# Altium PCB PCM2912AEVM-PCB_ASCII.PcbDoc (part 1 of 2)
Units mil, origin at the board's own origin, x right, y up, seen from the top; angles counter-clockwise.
Board outline 2362.2 x 944.88 mil, 4 copper layers (Top Layer, GND1 Layer, GND2 Layer, Bottom Layer), stack 58.906 mil thick; 73 components, 35 nets, 156 pads, 64 vias.
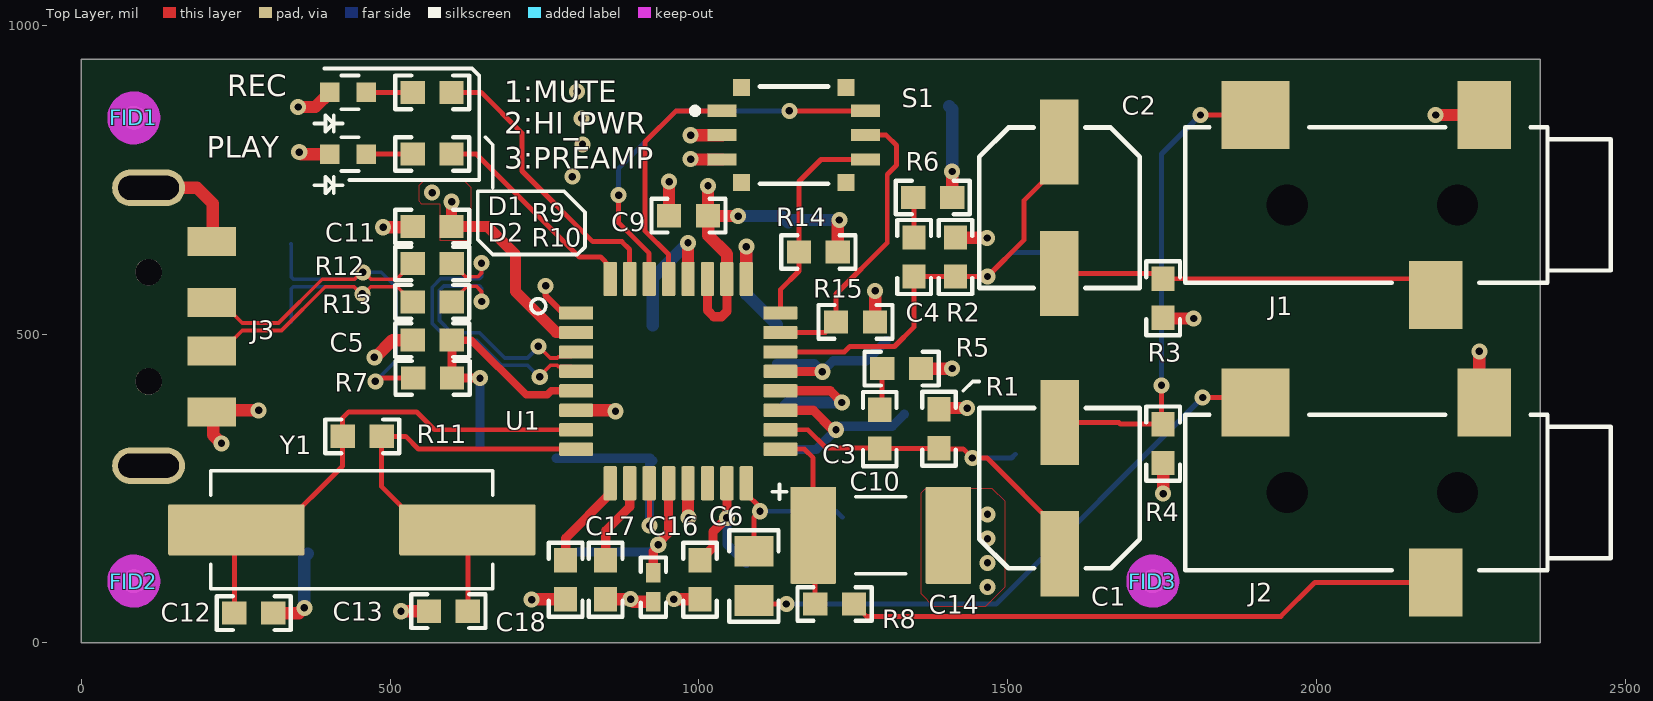
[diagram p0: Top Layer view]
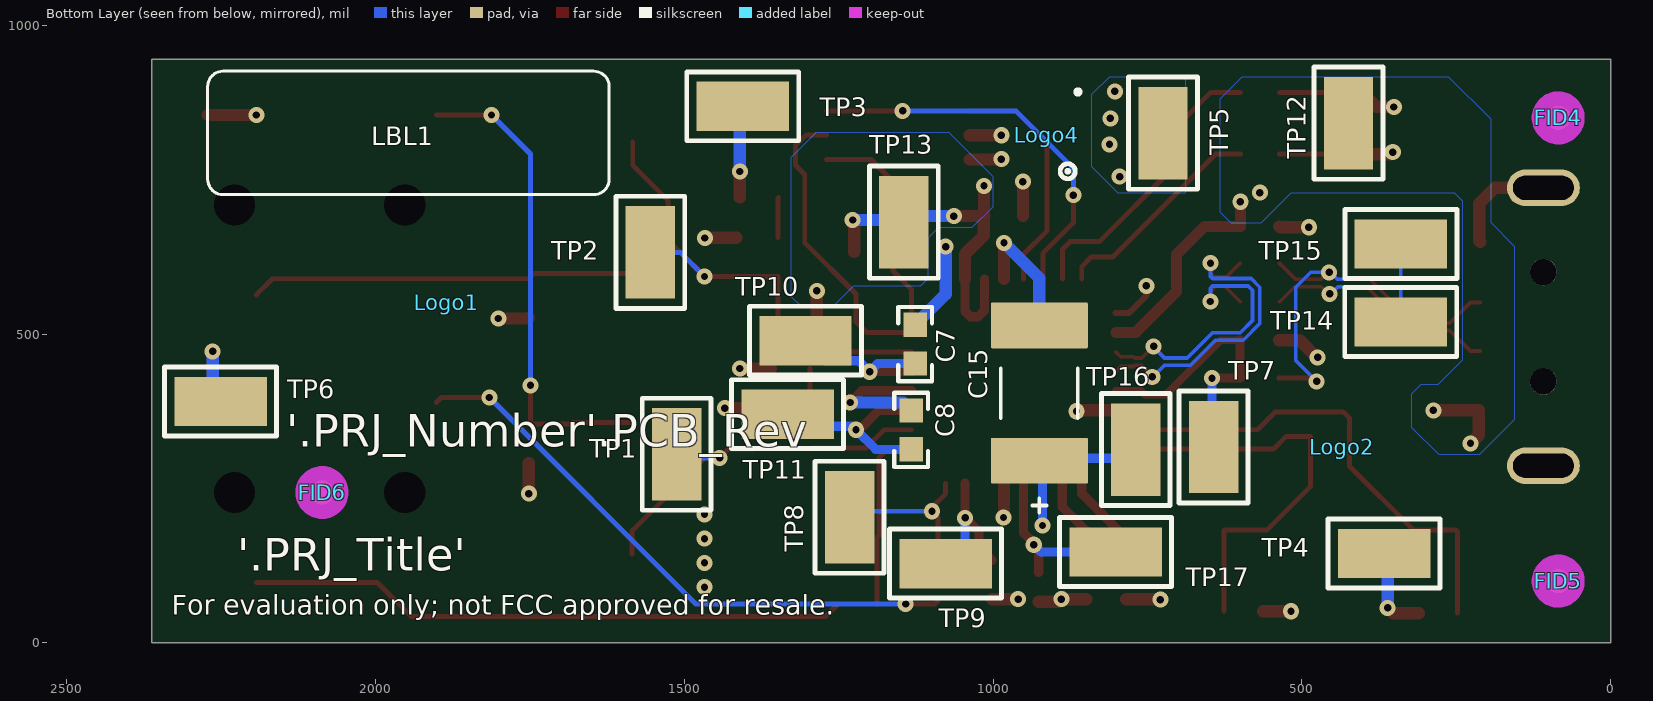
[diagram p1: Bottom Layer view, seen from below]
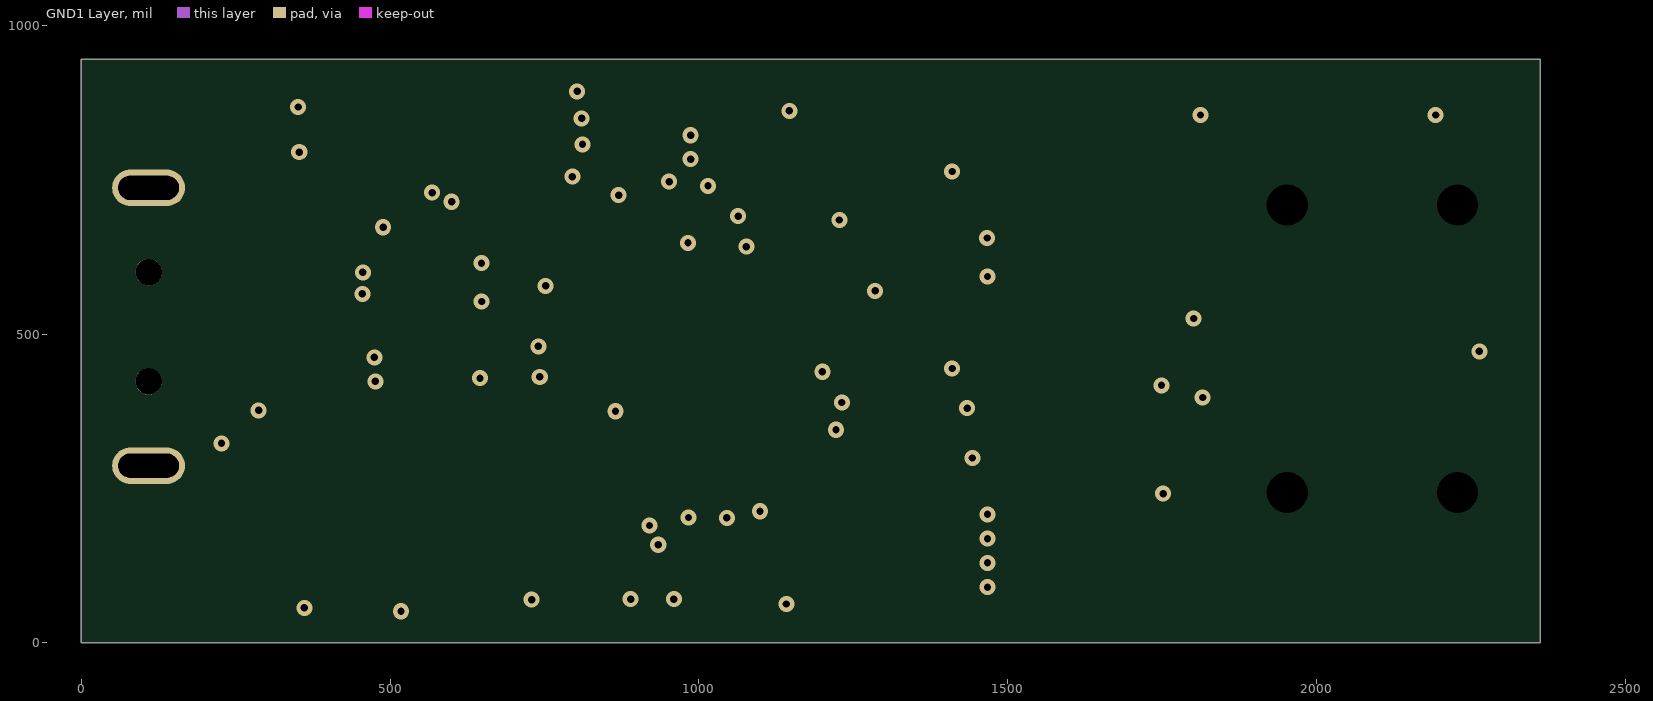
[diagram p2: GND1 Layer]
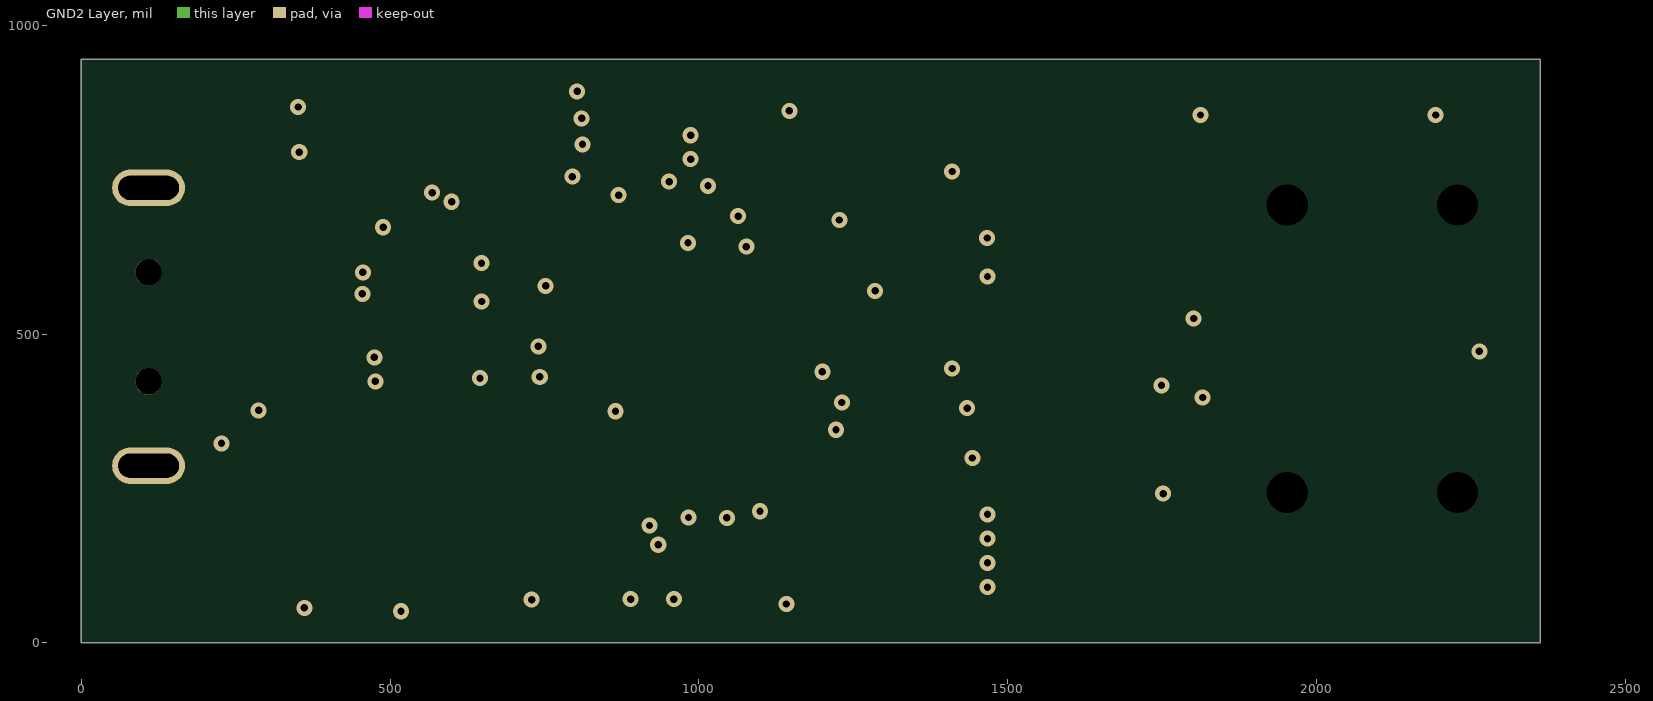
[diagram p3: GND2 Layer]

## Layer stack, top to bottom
Top Solder: solder mask 2, Solder Resist, Dk 3.5
Top Layer: signal copper 1.496
Dielectric 1: prepreg 4.313, FR-4 HIGH Tg, Dk 4.1
GND1 Layer: signal copper 1.4
Dielectric 2: core 44.488, FR-4 HIGH Tg, Dk 4.8
GND2 Layer: signal copper 1.4
Dielectric 3: prepreg 4.313, FR-4 HIGH Tg, Dk 4.1
Bottom Layer: signal copper 1.496
Bottom Solder: solder mask 2, Solder Resist, Dk 3.5

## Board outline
0,0 2362.2,0 2362.2,944.88 0,944.88

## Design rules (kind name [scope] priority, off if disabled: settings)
AcuteAngle [All] p0: scope1count=1 scope1_0_kind=Board scope1_0_value=Board scope2count=1 scope2_0_kind=Board scope2_0_value=Board commentlength=0 minimum=4.50000000000000E+0001
AcuteAngle [All] p1: minimum=4.50000000000000E+0001 checktracksonly=FALSE
AssemblyTestPointUsage [All] p0: scope1count=1 scope1_0_kind=Board scope1_0_value=Board scope2count=1 scope2_0_kind=Board scope2_0_value=Board commentlength=0
AssemblyTestPointUsage [All] p1: valid=2
AssemblyTestpoint [All] p0: scope1count=1 scope1_0_kind=Board scope1_0_value=Board scope2count=1 scope2_0_kind=Board scope2_0_value=Board commentlength=0
BoardOutlineClearance [All] p0 off: scope1count=1 scope1_0_kind=Board scope1_0_value=Board scope2count=1 scope2_0_kind=Board scope2_0_value=Board commentlength=172 gap=25 // Protel DXP Scope 1 Expression Was: OnCopper and Not InComponentClass('Logo') and not InComponentClass('FiducialMark') and not InRegion(1000,500,4000,800) and not InPoly
BoardOutlineClearance BoardOutlineClearance_Poly [All] p0 off: scope1count=1 scope1_0_kind=Board scope1_0_value=Board scope2count=1 scope2_0_kind=Board scope2_0_value=Board commentlength=58 gap=25 // Protel DXP Scope 1 Expression Was: OnCopper and IsPoly
BoardOutlineClearance BoardOutlineClearance_MountingHoles [All] p0 off: scope1count=1 scope1_0_kind=Board scope1_0_value=Board scope2count=1 scope2_0_kind=Board scope2_0_value=Board commentlength=86 gap=39.37 // Protel DXP Scope 1 Expression Was: OnCopper and InComponentClass('Mounting Holes')
BoardOutlineClearance BoardOutlineClearance_MountingHoles [OnCopper and InComponentClass('Mounting Holes')] p1: gap=39.37 ignorepadtopadclearanceinfootprint=FALSE
BoardOutlineClearance BoardOutlineClearance_Poly [OnCopper and IsPoly] p2: gap=25 ignorepadtopadclearanceinfootprint=FALSE
BoardOutlineClearance [OnCopper and Not InComponentClass('Logo') and not InComponentClass('FiducialMark') and not InRegion(1000,500,4000,800) and not InPoly] p3: gap=25 ignorepadtopadclearanceinfootprint=FALSE
Clearance [All] p0: scope1count=1 scope1_0_kind=Board scope1_0_value=Board scope2count=1 scope2_0_kind=Board scope2_0_value=Board commentlength=0 gap=10
Clearance Clearance_FiducialMark [All] p0 off: scope1count=1 scope1_0_kind=Board scope1_0_value=Board scope2count=1 scope2_0_kind=Board scope2_0_value=Board commentlength=81 gap=0 // Protel DXP Scope 2 Expression Was: IsPad and InComponentClass('FiducialMark')
Clearance Clearance_Keepouts [All] p0 off: scope1count=1 scope1_0_kind=Board scope1_0_value=Board scope2count=1 scope2_0_kind=Board scope2_0_value=Board commentlength=99 gap=0 // Protel DXP Scope 2 Expression Was: ((IsTrack Or IsArc) And Not InPoly) And IsFree and IsKeepOut
Clearance Clearance_Keepouts [((IsTrack Or IsArc) And Not InPoly) And IsFree and IsKeepOut vs ((IsTrack Or IsArc) And Not InPoly) And IsFree and IsKeepOut] p1: gap=0 ignorepadtopadclearanceinfootprint=FALSE
Clearance Clearance_FiducialMark [IsKeepOut and InComponentClass('FiducialMark') vs IsPad and InComponentClass('FiducialMark')] p2: gap=0 ignorepadtopadclearanceinfootprint=FALSE
Clearance [All] p3: gap=10 ignorepadtopadclearanceinfootprint=TRUE except(6: Track-Track; 8: Arc-Arc Arc-Track Arc-SMDPad Arc-THPad Arc-Via Arc-Fill Track-SMDPad Track-THPad Track-Via Track-Fill SMDPad-SMDPad SMDPad-THPad SMDPad-Via SMDPad-Fill THPad-THPad THPad-Via THPad-Fill Via-Via Via-Fill; 12: Arc-Poly Track-Poly SMDPad-Poly THPad-Poly Via-Poly; 15: Fill-Fill; 20: Fill-Poly; 25: Poly-Poly)
ComponentClearance [All] p0: scope1count=1 scope1_0_kind=Board scope1_0_value=Board scope2count=1 scope2_0_kind=Board scope2_0_value=Board commentlength=0 gap=30 collisioncheckmode=3
ComponentClearance ComponentClearance_THtoTH [All] p0 off: scope1count=1 scope1_0_kind=Board scope1_0_value=Board scope2count=1 scope2_0_kind=Board scope2_0_value=Board commentlength=54 gap=30 collisioncheckmode=3 // Protel DXP Scope 2 Expression Was: IsThruComponent
ComponentClearance ComponentClearance_THtoSMT [All] p0 off: scope1count=1 scope1_0_kind=Board scope1_0_value=Board scope2count=1 scope2_0_kind=Board scope2_0_value=Board commentlength=53 gap=40 collisioncheckmode=3 // Protel DXP Scope 2 Expression Was: IsSMTComponent
ComponentClearance ComponentClearance_SmallPassives [All] p0 off: scope1count=1 scope1_0_kind=Board scope1_0_value=Board scope2count=1 scope2_0_kind=Board scope2_0_value=Board commentlength=508 gap=14.96 collisioncheckmode=3 // Protel DXP Scope 2 Expression Was: HasFootprint('0201*') or HasFootprint('0402*') or HasFootprint('0508') or HasFootprint('0603*') or HasFootprint('0612') or HasFootprint('0805*') or HasFootprint('0815*') or HasFootprint('0830*') or HasFootprint('1206*') or HasFootprint('1210*') or HasFootprint('1808*') or HasFootprint('1812*') or HasFootprint('1825*') or HasFootprint('2010*') or HasFootprint('2220*') or HasFootprint('2225*') or HasFootprint('2512*') or HasFootprint('2728*') or HasFootprint('3518*')
ComponentClearance ComponentClearance_MountingHoles [All] p0: scope1count=1 scope1_0_kind=ComponentClass scope1_0_value="Mounting Holes" scope2count=1 scope2_0_kind=Board scope2_0_value=Board commentlength=0 gap=250 collisioncheckmode=3
ComponentClearance ComponentClearance_ScrewToNut [All] p0 off: scope1count=1 scope1_0_kind=Board scope1_0_value=Board scope2count=1 scope2_0_kind=Board scope2_0_value=Board commentlength=71 gap=5 collisioncheckmode=3 // Protel DXP Scope 2 Expression Was: (HasFootprint('Keystone_1902C'))
ComponentClearance ComponentClearance_Logo [All] p0: scope1count=1 scope1_0_kind=ComponentClass scope1_0_value=Logo scope2count=1 scope2_0_kind=Board scope2_0_value=Board commentlength=0 gap=50 collisioncheckmode=3
ComponentClearance ComponentClearance_Shunt [All] p0: scope1count=1 scope1_0_kind=ComponentClass scope1_0_value=Header scope2count=1 scope2_0_kind=ComponentClass scope2_0_value=Shunt commentlength=0 gap=0 collisioncheckmode=3
ComponentClearance ComponentClearance_MountingHoles_FiducialMarks [All] p0: scope1count=1 scope1_0_kind=ComponentClass scope1_0_value="Mounting Holes" scope2count=1 scope2_0_kind=ComponentClass scope2_0_value=FiducialMark commentlength=0 gap=50 collisioncheckmode=3
ComponentClearance ComponentClearance_MountingHoles_FiducialMarks [InComponentClass('Mounting Holes') vs InComponentClass('FiducialMark')] p1: gap=50 collisioncheckmode=3 verticalgap=10 showdistances=FALSE
ComponentClearance ComponentClearance_Shunt [InComponentClass('Header') vs InComponentClass('Shunt')] p2: gap=0 collisioncheckmode=3 verticalgap=0 showdistances=FALSE
ComponentClearance ComponentClearance_Logo [InComponentClass('Logo')] p3: gap=50 collisioncheckmode=3 verticalgap=10 showdistances=FALSE
ComponentClearance ComponentClearance_ScrewToNut [(HasFootprint('NY PMS 440 0025 PH')) vs (HasFootprint('Keystone_1902C'))] p4: gap=5 collisioncheckmode=3 verticalgap=10 showdistances=FALSE
ComponentClearance ComponentClearance_MountingHoles [InComponentClass('Mounting Holes')] p5: gap=250 collisioncheckmode=3 verticalgap=100000 showdistances=FALSE
ComponentClearance ComponentClearance_SmallPassives [HasFootprint('0201*') or HasFootprint('0402*') or HasFootprint('0508') or HasFootprint('0603*') or HasFootprint('0612') or HasFootprint('0805*') or HasFootprint('0815*') or HasFootprint('0830*') or HasFootprint('1206*') or HasFootprint('1210*') or HasFootprint('1808*') or HasFootprint('1812*') or HasFootprint('1825*') or HasFootprint('2010*') or HasFootprint('2220*') or HasFootprint('2225*') or HasFootprint('2512*') or HasFootprint('2728*') or HasFootprint('3518*') vs HasFootprint('0201*') or HasFootprint('0402*') or HasFootprint('0508') or HasFootprint('0603*') or HasFootprint('0612') or HasFootprint('0805*') or HasFootprint('0815*') or HasFootprint('0830*') or HasFootprint('1206*') or HasFootprint('1210*') or HasFootprint('1808*') or HasFootprint('1812*') or HasFootprint('1825*') or HasFootprint('2010*') or HasFootprint('2220*') or HasFootprint('2225*') or HasFootprint('2512*') or HasFootprint('2728*') or HasFootprint('3518*')] p6: gap=14.96 collisioncheckmode=3 verticalgap=10 showdistances=FALSE
ComponentClearance ComponentClearance_THtoSMT [IsThruComponent vs IsSMTComponent] p7: gap=40 collisioncheckmode=3 verticalgap=30 showdistances=FALSE
ComponentClearance ComponentClearance_THtoTH [IsThruComponent vs IsThruComponent] p8: gap=30 collisioncheckmode=3 verticalgap=30 showdistances=FALSE
ComponentClearance [All] p9: gap=30 collisioncheckmode=3 verticalgap=10 showdistances=FALSE
DiffPairsRouting [All] p0: scope1count=1 scope1_0_kind=Board scope1_0_value=Board scope2count=1 scope2_0_kind=Board scope2_0_value=Board commentlength=0
DiffPairsRouting [All] p1: maxlimit=100 minlimit=10 mostfreqgap=10 toplayer_minwidth=15 toplayer_maxwidth=15 toplayer_prefwidth=15 midlayer1_minwidth=15 midlayer1_maxwidth=15 midlayer1_prefwidth=15 midlayer2_minwidth=15 midlayer2_maxwidth=15 midlayer2_prefwidth=15 bottomlayer_minwidth=15 bottomlayer_maxwidth=15 bottomlayer_prefwidth=15 maxuncoupledlength=1000
FabricationTestPointUsage TestPointUsage [All] p0: scope1count=1 scope1_0_kind=Board scope1_0_value=Board scope2count=1 scope2_0_kind=Board scope2_0_value=Board commentlength=0 valid=2 allowmultiple=FALSE
FabricationTestPointUsage TestPointUsage [All] p1: valid=2 allowmultiple=FALSE
FabricationTestpoint Testpoint [All] p0: scope1count=1 scope1_0_kind=Board scope1_0_value=Board scope2count=1 scope2_0_kind=Board scope2_0_value=Board commentlength=0 side=3 testpointundercomponent=TRUE minsize=40 maxsize=100 preferedsize=60 minholesize=0 maxholesize=40 preferedholesize=32 testpointgrid=1
FabricationTestpoint Testpoint [All] p1: side=3 testpointundercomponent=TRUE minsize=40 maxsize=100 preferedsize=60 minholesize=0 maxholesize=40 preferedholesize=32 testpointgrid=1 allowsidetop=TRUE allowsidebottom=TRUE usegrid=TRUE gridtolerance=0.01
FanoutControl Fanout_Small [All] p0 off: scope1count=1 scope1_0_kind=Board scope1_0_value=Board scope2count=1 scope2_0_kind=Board scope2_0_value=Board commentlength=84 // Protel DXP Scope 1 Expression Was: (CompPinCount < 5)   Fanout_Small (Default Rule)
FanoutControl Fanout_Default [All] p0: scope1count=1 scope1_0_kind=Board scope1_0_value=Board scope2count=1 scope2_0_kind=Board scope2_0_value=Board commentlength=30 // Fanout_Default (Default Rule)
FanoutControl Fanout_SOIC [All] p0 off: scope1count=1 scope1_0_kind=Board scope1_0_value=Board scope2count=1 scope2_0_kind=Board scope2_0_value=Board commentlength=71 // Protel DXP Scope 1 Expression Was: IsSOIC   Fanout_SOIC (Default Rule)
FanoutControl Fanout_BGA [All] p0 off: scope1count=1 scope1_0_kind=Board scope1_0_value=Board scope2count=1 scope2_0_kind=Board scope2_0_value=Board commentlength=69 // Protel DXP Scope 1 Expression Was: IsBGA   Fanout_BGA (Default Rule)
FanoutControl Fanout_LCC [All] p0 off: scope1count=1 scope1_0_kind=Board scope1_0_value=Board scope2count=1 scope2_0_kind=Board scope2_0_value=Board commentlength=69 // Protel DXP Scope 1 Expression Was: IsLCC   Fanout_LCC (Default Rule)
FanoutControl Fanout_LCC [IsLCC] p1: bgadir=Out bgaviamode=Centered fanoutstyle=Auto fanoutdirection=Alternating viagrid=1 // Fanout_LCC (Default Rule)
FanoutControl Fanout_BGA [IsBGA] p2: bgadir=Out bgaviamode=Centered fanoutstyle=Auto fanoutdirection=Alternating viagrid=1 // Fanout_BGA (Default Rule)
FanoutControl Fanout_Default [All] p4: bgadir=Out bgaviamode=Centered fanoutstyle=Auto fanoutdirection=Alternating viagrid=1 // Fanout_Default (Default Rule)
FanoutControl Fanout_Small [(CompPinCount < 5)] p5: bgadir=Out bgaviamode=Centered fanoutstyle=Auto fanoutdirection=OutThenIn viagrid=1 // Fanout_Small (Default Rule)
Height [All] p0: scope1count=1 scope1_0_kind=Board scope1_0_value=Board scope2count=1 scope2_0_kind=Board scope2_0_value=Board commentlength=0
HoleSize [All] p0: scope1count=1 scope1_0_kind=Board scope1_0_value=Board scope2count=1 scope2_0_kind=Board scope2_0_value=Board commentlength=0 absolutevalues=TRUE maxlimit=251 minlimit=7.87 maxpercent=80.000 minpercent=20.000
HoleSize [All] p1: absolutevalues=TRUE maxlimit=251 minlimit=7.87 maxpercent=80.000 minpercent=20.000
HoleToHoleClearance [All] p0: scope1count=1 scope1_0_kind=Board scope1_0_value=Board scope2count=1 scope2_0_kind=Board scope2_0_value=Board commentlength=0
LayerPairs [All] p0: scope1count=1 scope1_0_kind=Board scope1_0_value=Board scope2count=1 scope2_0_kind=Board scope2_0_value=Board commentlength=0 enforce=TRUE
MinimumAnnularRing [All] p0: scope1count=1 scope1_0_kind=Board scope1_0_value=Board scope2count=1 scope2_0_kind=Board scope2_0_value=Board commentlength=0 minimumring=6
MinimumAnnularRing MinimumAnnularRing_ThermalPadVias [All] p0 off: scope1count=1 scope1_0_kind=Board scope1_0_value=Board scope2count=1 scope2_0_kind=Board scope2_0_value=Board commentlength=63 minimumring=5.91 // Protel DXP Scope 1 Expression Was: IsVia and InAnyComponent
MinimumAnnularRing MinimumAnnularRing_ThermalPadVias [IsVia and InAnyComponent] p1: minimumring=5.91
MinimumAnnularRing [All] p2: minimumring=6
MinimumSolderMaskSliver [All] p0: scope1count=1 scope1_0_kind=Board scope1_0_value=Board scope2count=1 scope2_0_kind=Board scope2_0_value=Board commentlength=0
MinimumSolderMaskSliver MinimumSolderMaskSliver_Logo [All] p0: scope1count=1 scope1_0_kind=ComponentClass scope1_0_value=Logo scope2count=1 scope2_0_kind=ComponentClass scope2_0_value=Logo commentlength=0
MinimumSolderMaskSliver MinimumSolderMaskSliver_Logo [InComponentClass('Logo') vs InComponentClass('Logo')] p1: minsoldermaskwidth=0.7
MinimumSolderMaskSliver [All] p2: minsoldermaskwidth=3.94
NetAntennae [All] p0: scope1count=1 scope1_0_kind=Board scope1_0_value=Board scope2count=1 scope2_0_kind=Board scope2_0_value=Board commentlength=0
PasteMaskExpansion [All] p0: scope1count=1 scope1_0_kind=Board scope1_0_value=Board scope2count=1 scope2_0_kind=Board scope2_0_value=Board commentlength=0 expansion=0
PlaneClearance [All] p0: scope1count=1 scope1_0_kind=Board scope1_0_value=Board scope2count=1 scope2_0_kind=Board scope2_0_value=Board commentlength=0 clearance=20
PlaneConnect [All] p0: scope1count=1 scope1_0_kind=Board scope1_0_value=Board scope2count=1 scope2_0_kind=Board scope2_0_value=Board commentlength=0 planeconnectstyle=Direct reliefexpansion=10 reliefentries=4 reliefconductorwidth=10 reliefairgap=10
PlaneConnect [All] p1: planeconnectstyle=Direct reliefexpansion=10 reliefentries=4 reliefconductorwidth=10 reliefairgap=10
PolygonConnect [All] p0: scope1count=1 scope1_0_kind=Board scope1_0_value=Board scope2count=1 scope2_0_kind=Board scope2_0_value=Board commentlength=0 connectstyle=Direct reliefconductorwidth=10 reliefentries=4 polygonreliefangle="90 Angle"
PolygonConnect [All] p1: connectstyle=Direct reliefconductorwidth=10 reliefentries=4 polygonreliefangle="90 Angle" airgapwidth=10
RoutingCorners [All] p0: scope1count=1 scope1_0_kind=Board scope1_0_value=Board scope2count=1 scope2_0_kind=Board scope2_0_value=Board commentlength=0 cornerstyle=45-Degree minsetback=100 maxsetback=100
RoutingLayers [All] p0: scope1count=1 scope1_0_kind=Board scope1_0_value=Board scope2count=1 scope2_0_kind=Board scope2_0_value=Board commentlength=0 top layer=Automatic mid layer 1=Automatic mid layer 2=Automatic bottom layer=Automatic
RoutingLayers [All] p1: top layer_v5=TRUE mid layer 1_v5=FALSE mid layer 2_v5=FALSE bottom layer_v5=TRUE
RoutingPriority [All] p0: scope1count=1 scope1_0_kind=Board scope1_0_value=Board scope2count=1 scope2_0_kind=Board scope2_0_value=Board commentlength=0
RoutingTopology [All] p0: scope1count=1 scope1_0_kind=Board scope1_0_value=Board scope2count=1 scope2_0_kind=Board scope2_0_value=Board commentlength=0 topology=Shortest
RoutingVias [All] p0: scope1count=1 scope1_0_kind=Board scope1_0_value=Board scope2count=1 scope2_0_kind=Board scope2_0_value=Board commentlength=0 holewidth=16 width=34 viastyle="Through Hole" minholewidth=7.87 minwidth=26 maxholewidth=40 maxwidth=65
RoutingVias ThermalPadVias [All] p0 off: scope1count=1 scope1_0_kind=Board scope1_0_value=Board scope2count=1 scope2_0_kind=Board scope2_0_value=Board commentlength=63 holewidth=7.87 width=19.68 viastyle="Through Hole" minholewidth=7.87 minwidth=19.68 maxholewidth=12.99 maxwidth=23.62 // Protel DXP Scope 1 Expression Was: IsVia and InAnyComponent
RoutingVias ThermalPadVias [IsVia and InAnyComponent] p1: holewidth=7.87 width=19.68 viastyle="Through Hole" minholewidth=7.87 minwidth=19.68 maxholewidth=12.99 maxwidth=23.62
RoutingVias [All] p2: holewidth=16 width=34 viastyle="Through Hole" minholewidth=7.87 minwidth=26 maxholewidth=40 maxwidth=65
ShortCircuit [All] p0: scope1count=1 scope1_0_kind=Board scope1_0_value=Board scope2count=1 scope2_0_kind=Board scope2_0_value=Board commentlength=0 allowed=FALSE
SilkToBoardRegionClearance [All] p0 off: scope1count=1 scope1_0_kind=Board scope1_0_value=Board scope2count=1 scope2_0_kind=Board scope2_0_value=Board commentlength=130 // Protel DXP Scope 1 Expression Was: Not ((IsComment or IsDesignator) And (Hide <> 'False')) and not InRegion(1000,500,4000,800)
SilkToBoardRegionClearance [Not ((IsComment or IsDesignator) And (Hide <> 'False')) and not InRegion(1000,500,4000,800)] p1:
SilkToSilkClearance [All] p0: scope1count=1 scope1_0_kind=Board scope1_0_value=Board scope2count=1 scope2_0_kind=Board scope2_0_value=Board commentlength=0
SilkToSilkClearance SilkToSilkClearance_Pb-FreeLogo [All] p0 off: scope1count=1 scope1_0_kind=Board scope1_0_value=Board scope2count=1 scope2_0_kind=Board scope2_0_value=Board commentlength=120 // Protel DXP Scope 2 Expression Was: (HasFootprint('Pb-Free_Overlay_Medium') OR HasFootprint('Pb-Free_Overlay_Small'))
SilkToSilkClearance SilkToSilkClearance_Pb-FreeLogo [(HasFootprint('Pb-Free_Overlay_Medium') OR HasFootprint('Pb-Free_Overlay_Small')) vs (HasFootprint('Pb-Free_Overlay_Medium') OR HasFootprint('Pb-Free_Overlay_Small'))] p1: silktosilkclearance=0
SilkToSilkClearance [All] p2: silktosilkclearance=3.94
SilkToSolderMaskClearance "Silk to Solder Mask Opening" [All] p0: scope1count=1 scope1_0_kind=Board scope1_0_value=Board scope2count=1 scope2_0_kind=Board scope2_0_value=Board commentlength=0
SilkToSolderMaskClearance SilkToComponentPadClearance [All] p0 off: scope1count=1 scope1_0_kind=Board scope1_0_value=Board scope2count=1 scope2_0_kind=Board scope2_0_value=Board commentlength=87 // Protel DXP Scope 1 Expression Was: (IsPad or IsFill or IsRegion) and InAnycomponent
SilkToSolderMaskClearance SilkToComponentPadClearance [(IsPad or IsFill or IsRegion) and InAnycomponent] p1: minsilkscreentomaskgap=2 clearancetoexposedcopper=TRUE
SilkToSolderMaskClearance "Silk to Solder Mask Opening" [All] p2: minsilkscreentomaskgap=0 clearancetoexposedcopper=FALSE
SolderMaskExpansion [All] p0: scope1count=1 scope1_0_kind=Board scope1_0_value=Board scope2count=1 scope2_0_kind=Board scope2_0_value=Board commentlength=0 expansion=1.97
SolderMaskExpansion [All] p1: expansion=1.97 istentingtop=FALSE
UnRoutedNet [All] p0: scope1count=1 scope1_0_kind=Board scope1_0_value=Board scope2count=1 scope2_0_kind=Board scope2_0_value=Board commentlength=0
UnRoutedNet [All] p1: checkbadconnections=TRUE
UnpouredPolygon [All] p0: scope1count=1 scope1_0_kind=Board scope1_0_value=Board scope2count=1 scope2_0_kind=Board scope2_0_value=Board commentlength=0
Width [All] p0: scope1count=1 scope1_0_kind=Board scope1_0_value=Board scope2count=1 scope2_0_kind=Board scope2_0_value=Board commentlength=0 maxlimit=100 minlimit=6 preferedwidth=10
Width [All] p1: maxlimit=100 minlimit=6 preferedwidth=10 checkconnectedcopper=TRUE
13 further rules are at their usual default settings.

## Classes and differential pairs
component class PCM2912AEVM-Schematic: C1 C2 C3 C4 C5 C6 C7 C8 C9 C10 C11 C12 C13 C14 C15 C16 C17 C18 D1 D2 J1 J2 J3 R1 R2 R3 R4 R5 R6 R7 R8 R9 R10 R11 R12 R13 R14 R15 S1 TP1 TP2 TP3 TP4 TP5 TP6 TP7 TP8 TP9 TP10 TP11 TP12 TP13 TP14 TP15 TP16 TP17 U1 Y1
component class Logo: Logo1
component class PCM2912AEVM-Hardware: FID1 FID2 FID3 FID4 FID5 FID6 LBL1 Logo1 Logo2 Logo3 Logo4 ZZ1 ZZ2 ZZ3 ZZ4
component class FiducialMark: FID1 FID2 FID3 FID4 FID5 FID6
component class AssemblyNote: ZZ1 ZZ2 ZZ3 ZZ4
component class Label: LBL1

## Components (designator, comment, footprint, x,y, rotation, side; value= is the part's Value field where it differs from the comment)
C1 "6SVP100M" SM_RADIAL_6.3AMM 1584.34,250.52 r90 top
C2 "6SVP100M" SM_RADIAL_6.3AMM 1583.5,704.54 r270 top
C3 "C0603C223K3RACTU" 0603 1292.85,346.18 r90 top
C4 "C0603C223K3RACTU" 0603 1348.57,624.74 r90 top
C5 "C1608X7R1C105K080AC" 0603 568.29,490.22 r180 top
C6 "C1608X7R1C105K080AC" 0603 1001.62,102.17 r270 top
C7 "C1608X7R1C105K080AC" 0603 1126.07,483.74 r90 bottom
C8 "C1608X7R1C105K080AC" 0603 1132.57,344.75 r90 bottom
C9 "C1608X7R1C105K080AC" 0603 983.17,691.62 r180 top
C10 "0805ZD335KAT2A" 0805_HV 1088.99,108.34 r270 top
C11 "C1608X7R1C105K080AC" 0603 568.07,674.22 r180 top
C12 "06035A220JAT2A" 0603 279.32,48.04 r180 top
C13 "06035A220JAT2A" 0603 594.41,51.2 r0 top
C14 "TAZG106K025CRSZ0000" TAZG106K025CRSZ0000-Footprint-1 1294.47,174.18 r180 top
C15 "TAZG106K025CRSZ0000" TAZG106K025CRSZ0000-Footprint-1 925.08,404.5 r270 bottom
C16 "LMK105BJ104KV-F" 0402 926.18,90.18 r270 top
C17 "06033C101KAT2A" 0603 849.07,102.17 r270 top
C18 "06033C101KAT2A" 0603 784.21,102.17 r270 top
D1 "LTST-C193KRKT-5A" LTST-C193_Red 432.15,891.37 r0 top
D2 "LTST-C193KGKT-5A" LTST-C193_Green 432.15,791.37 r0 top
FID1 "Fiducial" Fiducial10-20 85,850 r0 top
FID2 "Fiducial" Fiducial10-20 85,100 r0 top
FID3 "Fiducial" Fiducial10-20 1735,100 r0 top
FID4 "Fiducial" Fiducial10-20 85,850 r180 bottom
FID5 "Fiducial" Fiducial10-20 85,100 r180 bottom
FID6 "Fiducial" Fiducial10-20 2086.61,243.5 r180 bottom
J1 "SJ-3523-SMT" CUI_SJ-3523-SMT 2086.61,709.07 r180 top locked
J2 "SJ-3523-SMT" CUI_SJ-3523-SMT 2086.61,243.5 r180 top locked
J3 "48037-1000" CONN_USB-A-48037-1000 122.75,511.81 r180 top locked
LBL1 "THT-14-423-10" Label_650x200 1946.79,825.73 r180 bottom
Logo1 "Texas Instruments" TI_Stacked_Overlay_Small 1885,551 r180 bottom
Logo2 "CE Mark" CE_Mark_5mm 435,317.17 r180 bottom
Logo3 "FCC disclaimer" FCC_disclaimer 963.47,-770 r180 bottom
Logo4 "WEEE logo" WEEE_Minimum 913.27,821.94 r180 bottom
R1 "CRCW06033K30JNEA" 0603 1388.75,346.53 r270 top
R2 "CRCW06033K30JNEA" 0603 1415.51,624.74 r270 top
R3 "CRCW06033K30JNEA" 0603 1751.71,558.01 r90 top
R4 "CRCW06033K30JNEA" 0603 1751.71,322.66 r90 top
R5 "RC0603FR-0716RL" 0603 1328.2,444.06 r180 top
R6 "RC0603FR-0716RL" 0603 1378.57,721.03 r180 top
R7 "CRCW06031K50JNEA" 0603 568.81,428.99 r0 top
R8 "CRCW06031K00JNEA" 0603 1219.65,62.97 r0 top
R9 "CRCW0603820RJNEA" 0603 568.07,891.37 r0 top
R10 "CRCW0603820RJNEA" 0603 568.07,791.37 r0 top
R11 "CRCW06031M00JNEA" 0603 454.78,334.45 r0 top
R12 "CRCW060333R0JNEA" 0603 568.24,614.3 r0 top
R13 "CRCW060333R0JNEA" 0603 568.29,552.22 r0 top
R14 "CRCW060310K0JNEA" 0603 1193.56,632.76 r0 top
R15 "CRCW060310K0JNEA" 0603 1253.52,519.78 r0 top
S1 "CVS-03TB" SW_CVS-03B 1153.75,822.1 r0 top
TP1 "5019" Keystone_5019 1512.33,305.41 r90 bottom
TP2 "5019" Keystone_5019 1555.09,632.34 r270 bottom
TP3 "5019" Keystone_5019 1405.33,868.61 r180 bottom
TP4 "5019" Keystone_5019 366.88,144.66 r180 bottom
TP5 "5019" Keystone_5019 725.02,825.31 r270 bottom
TP6 "5019" Keystone_5019 2250.85,390.68 r180 bottom
TP7 "5019" Keystone_5019 643.02,317.17 r270 bottom
TP8 "5019" Keystone_5019 1232.39,203.37 r90 bottom
TP9 "5019" Keystone_5019 1076.9,128.36 r180 bottom
TP10 "5019" Keystone_5019 1303.82,489.27 r0 bottom
TP11 "5019" Keystone_5019 1332.71,370.31 r180 bottom
TP12 "5019" Keystone_5019 424.53,841.4 r90 bottom
TP13 "5019" Keystone_5019 1144.57,681.14 r270 bottom
TP14 "5019" Keystone_5019 339.99,519.54 r180 bottom
TP15 "5019" Keystone_5019 339.66,645.84 r0 bottom
TP16 "5019" Keystone_5019 769.07,312.91 r270 bottom
TP17 "5019" Keystone_5019 801.61,147.14 r180 bottom
U1 "PCM2912APJTR" PJT0032A 966.66,423.8 r0 top
Y1 "ABLS2-6.000MHZ-D4Y-T" FP-ABLS2-6.000MHZ-D4Y-T_SMT_11MM4_4MM7-MFG 438.01,183.05 r0 top
ZZ1 "This Assembly Note is for PCB labels only" AssemblyNoteLabel -996.1,3347.45 r0 top
ZZ2 "These assemblies are ESD sensitive, ESD precautions shall be observed." AssemblyNote -996.1,3238.56 r0 top
ZZ3 "These assemblies must be clean and free from flux and all contaminants. Use of no clean flux is not acceptable." AssemblyNote -996.1,3150.01 r0 top
ZZ4 "These assemblies must comply with workmanship standards IPC-A-610 Class 2, unless otherwise specified." AssemblyNote -996.1,3061.45 r0 top

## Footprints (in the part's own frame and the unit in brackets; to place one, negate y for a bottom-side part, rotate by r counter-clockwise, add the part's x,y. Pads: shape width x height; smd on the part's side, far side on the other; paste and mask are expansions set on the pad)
0402 [mm] "0402 from SM-752 data"
  rect 0.8x0.6 smd: 1(-0.6,0) 2(0.6,0)
  silkscreen extent -1.22,-0.52 1.22,0.52
0603 [mm] "0603 from SM-752 data"
  rect 1x0.95 smd: 1(-0.8,0) 2(0.8,0)
  silkscreen extent -1.52,-0.69 1.52,0.69
0805_HV [mil] "0805 with 30mil clearance between pads"
  rect 50x63 smd: 1(-40,0) 2(40,0)
  silkscreen extent -74,-40 74,40
AssemblyNote [mil] "Assembly Note"
AssemblyNoteLabel [mil] "Assembly Note for PCB Labels"
CE_Mark_5mm [mil] "Minimum text height for CE Mark"
CONN_USB-A-48037-1000 [mm] "Molex"
  rect 2x1.2 smd: 1(-2.25,3.5) 2(-2.25,1) 3(-2.25,-1) 4(-2.25,-3.5)
  oval 3x1.5 hole 1 slot 2.5 at 0 deg: 5(0.35,5.715) 6(0.35,-5.715)
  round 1.092 hole 1.092 unplated: 7(0.35,2.248) 8(0.35,-2.248)
CUI_SJ-3523-SMT [mm] "CUI recommended land pattern Rev C CUI_SJ-3523-SMT_Datasheet.pdf"
  rect 2.2x2.8 smd: 1(-4.7,-3.7) 3(-2.7,3.7)
  rect 2.8x2.8 smd: 2(4.7,-3.7)
  round 0 hole 1.7 unplated mask+0: 4(-3.6,0) 5(3.4,0)
  silkscreen extent -9.9,-3.2 7.6,3.2
FCC_disclaimer [mil]
Fiducial10-20 [mm]
  round 1 smd mask+0: 1(0,0)
  Top Layer keep-out circle w1.178: c0,0 r0.5
FP-ABLS2-6.000MHZ-D4Y-T_SMT_11MM4_4MM7-MFG [mm]
  rrect5% 5.6x2.1 smd paste+0 mask+0: 1(-4.75,0) 2(4.75,0)
  silkscreen extent -5.8,-2.43 5.8,2.43
Keystone_5019 [mm] "Test Point, Miniature, SMT"
  rect 3.8x2.03 smd: 1(0,0)
  silkscreen extent -2.31,-1.42 2.31,1.42
Label_650x200 [mil] "Thermal Transfer Label"
  round 1 on Mech14: 0(0,0)
  silkscreen extent -325,-100 325,100
LTST-C193_Green [mm] "SMD, 2-Leads, Body1.6x0.8mm"
  rect 0.8x0.8 smd: 1(-0.75,0) 2(0.75,0)
LTST-C193_Red [mm] "SMD, 2-Leads, Body1.6x0.8mm"
  rect 0.8x0.8 smd: 1(-0.75,0) 2(0.75,0)
PJT0032A [mm] "TQFP, 32-Leads, Body 7x7.mm, Pitch 0.8mm"
  rrect18% 1.4x0.55 smd: 1(-4.2,2.8) 2(-4.2,2) 3(-4.2,1.2) 4(-4.2,0.4) 5(-4.2,-0.4) 6(-4.2,-1.2) 7(-4.2,-2) 8(-4.2,-2.8) 17(4.2,-2.8) 18(4.2,-2) 19(4.2,-1.2) 20(4.2,-0.4) 21(4.2,0.4) 22(4.2,1.2) 23(4.2,2) 24(4.2,2.8)
  rrect18% 0.55x1.4 smd: 9(-2.8,-4.2) 10(-2,-4.2) 11(-1.2,-4.2) 12(-0.4,-4.2) 13(0.4,-4.2) 14(1.2,-4.2) 15(2,-4.2) 16(2.8,-4.2) 25(2.8,4.2) 26(2,4.2) 27(1.2,4.2) 28(0.4,4.2) 29(-0.4,4.2) 30(-1.2,4.2) 31(-2,4.2) 32(-2.8,4.2)
SM_RADIAL_6.3AMM [mm] "Nichicon 6.3x5.8"
  rect 3.5x1.6 smd: 1(-2.7,0) 2(2.7,0)
  silkscreen extent -3.3,-3.29 3.3,3.31
SW_CVS-03B [mm] "Copal Electronics"
  rect 1.2x0.5 smd: 1(-2.95,1) 2(-2.95,0) 3(-2.95,-1) 4(2.95,-1) 5(2.95,0) 6(2.95,1)
  rect 0.7x0.7 smd: M1(-2.15,1.95) M2(-2.15,-1.95) M3(2.15,-1.95) M4(2.15,1.95)
  silkscreen extent -4.19,-2 1.4,2
TAZG106K025CRSZ0000-Footprint-1 [mil]
  rrect5% 74x157 smd paste+0 mask+0: 1(-109.5,0) 2(109.5,0)
  silkscreen extent -40,-82 176,62
TI_Stacked_Overlay_Small [mil]
WEEE_Minimum [mil] "WEEElie bin"
  silkscreen extent 22,-71 54,74

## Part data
C1 C2: library part CMP-0012149-3, "CAP, Aluminum Polymer, 100 uF, 6.3 V, +/- 20%, 0.04 ohm, 6.3x5.8 SMD"
C3 C4: library part CMP-0006899-1, "CAP, CERM, 0.022 uF, 25 V, +/- 10%, X7R, 0603"
C5 C6 C7 C8 C9 C11: library part CMP-0007037-4, "CAP, CERM, 1 uF, 16 V, +/- 10%, X7R, 0603"
C10: library part CMP-0007686-2, "CAP, CERM, 3.3 uF, 10 V, +/- 10%, X5R, 0805"
C12 C13: library part CMP-0006775-4, "CAP, CERM, 22 pF, 50 V, +/- 5%, C0G/NP0, 0603"
C14 C15: library part CMP-0089355-2, "10µF Molded Tantalum Capacitors 25V 0201 (0603 Metric) 1.4Ohm @ 100kHz"
C16: library part CMP-0064930-2, "CAP, CERM, 0.1 uF, 10 V,+/- 10%, X5R, 0402"
C17 C18: library part CMP-0006751-1, "CAP, CERM, 100 pF, 25 V, +/- 10%, X7R, 0603"
D1: library part CMP-0079922-2, "LED, Red, SMD"
D2: library part CMP-0079921-2, "LED, Green, SMD"
FID1 FID2 FID3 FID4 FID5 FID6: library part CMP-0077181-1, "Fiducial mark.  There is nothing to buy or mount."
J1 J2: library part CMP-0074907-1, "Audio Jack, 3.5mm, Stereo, R/A, SMT"
J3: library part CMP-0055294-1, "Connector, Plug, USB Type A, R/A, Top Mount SMT"
LBL1: library part CMP-0003625-1, "Thermal Transfer Printable Labels, 0.650\" W x 0.200\" H - 10,000 per roll"
Logo1: library part CMP-0074838-1, "Texas Instrument Corporate Signature"
Logo2: library part CMP-0074844-1
Logo3: library part CMP-0074847-1, "FCC_disclaimer"
Logo4: library part CMP-0074769-1
R1 R2 R3 R4: library part CMP-0025797-4, "RES, 3.3 k, 5%, 0.1 W, AEC-Q200 Grade 0, 0603"
R5 R6: library part CMP-0022835-4, "RES, 16.0, 1%, 0.1 W, 0603"
R7: library part CMP-0025733-4, "RES, 1.5 k, 5%, 0.1 W, AEC-Q200 Grade 0, 0603"
R8: library part CMP-0025729-3, "RES, 1.0 k, 5%, 0.1 W, 0603"
R9 R10: library part CMP-0025859-3, "RES, 820, 5%, 0.1 W, 0603"
R11: library part CMP-0025736-4, "RES, 1.0 M, 5%, 0.1 W, AEC-Q200 Grade 0, 0603"
R12 R13: library part CMP-0025787-1, "RES, 33, 5%, 0.1 W, 0603"
R14 R15: library part CMP-0025701-2, "RES, 10 k, 5%, 0.1 W, 0603"
S1: library part CMP-0002165-2, "DIP Switch, SPST, 3Pos, Slide, SMT"
TP1 TP2 TP3 TP4 TP5 TP6 TP7 TP8 TP9 TP10 TP11 TP12 TP13 TP14 TP15 TP16 TP17: library part CMP-0055162-1, "Test Point, Miniature, SMT"
U1: library part CMP-0086356-1, "Audio CODEC with USB Interface, Mono Microphone Input and Stereo Headphone Output, PJT0032A (TQFP-32)"
Y1: library part CMP-0092892-1, "6 MHz ±30ppm Crystal 18pF 100 Ohms HC-49/US"
ZZ1: library part CMP-0003616-3
ZZ2: library part CMP-0077236-1
ZZ3: library part CMP-0077237-1
ZZ4: library part CMP-0077238-1

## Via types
v1: diameter 26, hole 12, Top Layer to Bottom Layer, tented both sides, 64 vias

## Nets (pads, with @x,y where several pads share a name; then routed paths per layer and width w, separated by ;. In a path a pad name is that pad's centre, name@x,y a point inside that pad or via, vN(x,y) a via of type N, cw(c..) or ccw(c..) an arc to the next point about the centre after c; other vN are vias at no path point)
GND: C5.2 C6.2 C7.2 C8.2 C9.2 C11.2 C12.1 C13.1 C14.1 C15.1 C16.2 C17.2 C18.2 J1.1 J2.1 J3.4 J3.5 J3.6 R1.1 R2.1 R3.1 R4.1 R5.1 R6.1 S1.2 S1.3 TP3.1 TP4.1 TP5.1 TP6.1 U1.1 U1.6 U1.13 U1.20 U1.25 U1.28 | length 2297
  Top Layer w10: v1(751.85,578) 751.85,562.27 780.09,534.03 U1.1@801.31,534.03
  Top Layer w15: U1.20@1132.02,408.05 1212.58,408.05 v1(1231.46,389.17)
  Top Layer w20: J3.6@108.97,736.81 187.32,736.81 212.81,711.32 212.81,651.09 J3.4@211.33,649.61 ; C12.1@310.82,48.04 352.61,48.04 v1(361.24,56.67) ; v1(474.42,462.16) 476.04,462.16 504.1,490.22 C5.2@536.79,490.22 ; v1(488.78,672.92) 535.28,672.92 C11.2@536.58,674.22 ; v1(517.63,51.2) C13.1@562.91,51.2 ; v1(729.25,69.91) 730.02,70.67 C18.2@784.21,70.67 ; U1.6@801.31,376.55 863.45,376.55 v1(865,375) ; C17.2@849.07,70.67 v1(889.4,70.67) 893.51,66.56 C16.2@926.18,66.56 ; C9.2@951.67,691.62 v1(951.67,746.81) ; v1(959.45,70.67) C6.2@1001.62,70.67 ; U1.13@982.41,260.8 982.41,203.76 v1(983.17,203) ; U1.28@982.41,589.15 v1(982.41,647.77) ; v1(986.64,783.21) 987.12,782.73 S1.3@1037.61,782.73 S1.3@1037.77,782.57 ; v1(986.64,821.94) S1.2@1037.77,821.94 ; U1.25@1076.9,589.15 v1(1076.9,641.57) ; R5.1@1359.7,444.06 1409.84,444.06 v1(1410.07,444.29) ; R1.1@1388.75,378.02 1390.91,380.18 v1(1434.21,380.18) ; R6.1@1410.07,721.03 v1(1410.07,763.22) ; R2.1@1415.51,656.23 1415.86,655.88 1466.26,655.88 v1(1466.62,655.52) ; v1(1751.71,241.71) R4.1@1751.71,291.16 ; R3.1@1751.71,526.51 1753.07,525.15 v1(1801,525.15) ; v1(2192.91,854.74) J1.1@2271.65,854.74 ; v1(2263.77,471.86) 2263.77,397.04 J2.1@2271.65,389.17
  Bottom Layer w20: v1(361.24,56.67) 361.24,139.02 TP4.1@366.88,144.66 ; C15.1@925.08,514 925.08,590.45 v1(982.41,647.77) ; v1(1076.9,641.57) 1076.9,564.41 C7.2@1126.07,515.24 ; C8.2@1132.57,376.25 1145.49,389.17 v1(1231.46,389.17) ; TP3.1@1405.33,868.61 1410.07,863.87 v1(1410.07,763.22) ; TP6.1@2250.85,390.68 2263.77,403.61 v1(2263.77,471.86)
  other v1: 1467.31,90.35 1467.31,129.55 1467.31,168.75 1467.31,207.95 795,755 811.52,807.16 810,849.21 802.83,893.05
MUTE: S1.1 U1.29 | length 383.7
  Top Layer w8: U1.29@950.91,589.15 950.91,628.71 912.49,667.14 912.49,810.86 963.1,861.47 S1.1@1037.61,861.47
